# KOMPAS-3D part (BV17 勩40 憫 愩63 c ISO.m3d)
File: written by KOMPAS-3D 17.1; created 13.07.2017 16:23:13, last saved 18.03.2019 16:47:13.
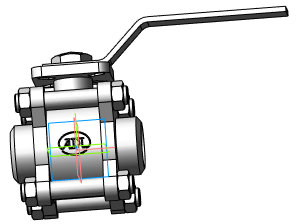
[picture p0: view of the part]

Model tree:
1. Операция без истории:2  (labels: Сталь 20  ГОСТ 1050-88)

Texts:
  DISO1
  DISO2
  BV17 Ду8 1/4" Ру63
  BV17 Ду8 СС Ру63
  BV17 Ду10 3/8" Ру63
  BV17 Ду10 СС Ру63
  BV17 Ду15 1/2" Ру63
  BV17 Ду15 СС Ру63
  BV17 Ду15 ФФ Ру40
  BV17 Ду20 3/4" Ру63
  BV17 Ду20 СС Ру40
  BV17 Ду20 ФФ Ру40
  BV17 Ду25 1" Ру63
  BV17 Ду25 СС Ру63
  BV17 Ду25 ФФ Ру40
  BV17 Ду32 1 1/4" Ру63
  BV17 Ду32 СС Ру63
  BV17 Ду32 ФФ Ру40
  BV17 Ду40 1 1/2" Ру63
  BV17 Ду40 СС Ру63
  BV17 Ду40 ФФ Ру40
  BV17 Ду50 2" Ру63
  BV17 Ду50 СС Ру63
  BV17 Ду50 ФФ Ру40
  BV17 Ду65 2 1/2" Ру40
  BV17 Ду65 СС Ру40
  BV17 Ду65 ФФ Ру40
  BV17 Ду80 3" Ру40
  BV17 Ду80 СС Ру40
  BV17 Ду80 ФФ Ру40
  BV17 Ду100 4" Ру40
  BV17 Ду100 СС Ру40
  BV17 Ду100 ФФ Ру40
